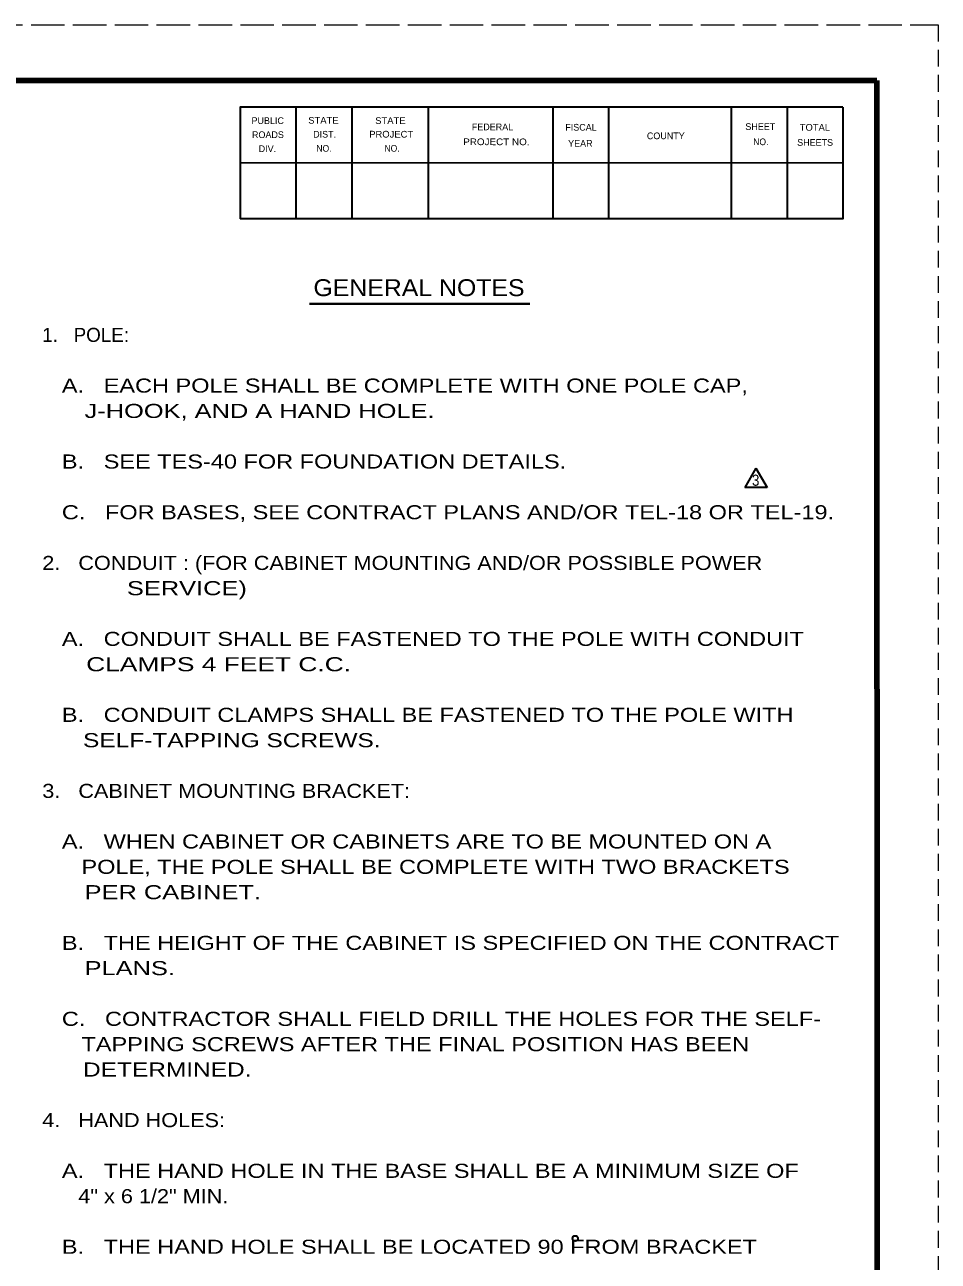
# Model space of a CAD drawing. Extents: x -1 to 679, y -228 to 440.
# Drawn here: x 515.4 to 679, y 218.8 to 440.2 of the extents above; entities that cross this region are included whole.
import ezdxf

# ---------------------------------------------------------------- set-up
doc = ezdxf.new("R2010")
doc.units = 0
doc.linetypes.add('LONG_DASHED', pattern=[7.5, 6, -1.5])
doc.linetypes.add('MEDIUM_DASHED', pattern=[4.5, 3, -1.5])
doc.layers.add('1', color=7, linetype='Continuous', lineweight=35)
doc.layers.add('61', color=7, linetype='Continuous', lineweight=35)

msp = doc.modelspace()

# ---------------------------------------------------------------- linework, layer by layer
at = {"layer": '1', "linetype": 'MEDIUM_DASHED', "lineweight": 13}
msp.add_line((679.041, 440.237), (679.021, 0.217), dxfattribs=at)
at = {"layer": '1', "lineweight": 40}
msp.add_line((566.411, 390.257), (605.851, 390.257), dxfattribs=at)
at = {"layer": '1'}
for p, q in [((646.385, 360.85), (644.385, 357.386)), ((646.385, 360.85), (648.385, 357.386)), ((648.385, 357.386), (644.385, 357.386))]:
    msp.add_line(p, q, dxfattribs=at)
msp.add_circle((614.003, 222.892), 0.481, dxfattribs=at)
at = {"layer": '61', "linetype": 'LONG_DASHED', "lineweight": 13}
msp.add_line((-0.979, 440.237), (679.041, 440.237), dxfattribs=at)
at = {"layer": '61', "lineweight": 158}
msp.add_line((668.061, 430.237), (668.081, 10.197), dxfattribs=at)
at = {"layer": '61'}
for p, q in [((563.981, 425.477), (563.981, 405.477)), ((573.981, 425.477), (573.981, 405.477)), ((587.661, 425.477), (587.661, 405.477)), ((609.981, 425.477), (609.981, 405.477)), ((619.981, 425.477), (619.981, 405.477)), ((641.961, 425.497), (641.961, 405.497)), ((651.961, 425.497), (651.961, 405.497)), ((661.981, 415.457), (553.961, 415.477))]:
    msp.add_line(p, q, dxfattribs=at)
at = {"layer": '61', "lineweight": 158}
msp.add_lwpolyline([(668.061, 430.237), (29.021, 430.237), (29.021, 10.217)], dxfattribs=at)
at = {"layer": '61'}
for points in [[(661.961, 425.497), (553.981, 425.477), (553.981, 405.477)], [(661.961, 425.497), (661.961, 405.497), (553.981, 405.477)]]:
    msp.add_lwpolyline(points, dxfattribs=at)

# ---------------------------------------------------------------- texts
at = {"layer": '1'}
for s, height, width, p in [('GENERAL NOTES', 3.024, 1.1, (567.111, 391.637)), ('   A.   EACH POLE SHALL BE COMPLETE WITH ONE POLE CAP,', 2.52, 1.25, (518.531, 374.357)), ('      J-HOOK, AND A HAND HOLE.', 2.52, 1.35, (518.531, 369.817)), ('   B.   SEE TES-40 FOR FOUNDATION DETAILS.', 2.52, 1.25, (518.531, 360.757)), ('3', 2, 0.9, (645.66, 357.67)), ('   C.   FOR BASES, SEE CONTRACT PLANS AND/OR TEL-18 OR TEL-19.', 2.52, 1.25, (518.531, 351.677)), ('2.   CONDUIT : (FOR CABINET MOUNTING AND/OR POSSIBLE POWER', 2.52, 1.15, (518.531, 342.597)), ('            SERVICE)', 2.52, 1.35, (518.531, 338.077)), ('   A.   CONDUIT SHALL BE FASTENED TO THE POLE WITH CONDUIT', 2.52, 1.25, (518.531, 328.997)), ('      CLAMPS 4 FEET C.C.', 2.52, 1.4, (518.531, 324.457)), ('   B.   CONDUIT CLAMPS SHALL BE FASTENED TO THE POLE WITH', 2.52, 1.25, (518.531, 315.397)), ('      SELF-TAPPING SCREWS.', 2.52, 1.3, (518.531, 310.857)), ('3.   CABINET MOUNTING BRACKET:', 2.52, 1.15, (518.531, 301.777)), ('   A.   WHEN CABINET OR CABINETS ARE TO BE MOUNTED ON A', 2.52, 1.25, (518.531, 292.717)), ('      POLE, THE POLE SHALL BE COMPLETE WITH TWO BRACKETS', 2.52, 1.25, (518.531, 288.177)), ('      PER CABINET.', 2.52, 1.35, (518.531, 283.637)), ('   B.   THE HEIGHT OF THE CABINET IS SPECIFIED ON THE CONTRACT', 2.52, 1.25, (518.531, 274.557)), ('      PLANS.', 2.52, 1.35, (518.531, 270.037)), ('   C.   CONTRACTOR SHALL FIELD DRILL THE HOLES FOR THE SELF-', 2.52, 1.25, (518.531, 260.957)), ('      TAPPING SCREWS AFTER THE FINAL POSITION HAS BEEN', 2.52, 1.25, (518.531, 256.417)), ('      DETERMINED.', 2.52, 1.3, (518.531, 251.877)), ('4.   HAND HOLES:', 2.52, 1.15, (518.531, 242.817)), ('   A.   THE HAND HOLE IN THE BASE SHALL BE A MINIMUM SIZE OF', 2.52, 1.25, (518.531, 233.737)), ('      4" x 6 1/2" MIN.', 2.52, 1.15, (518.531, 229.197)), ('   B.   THE HAND HOLE SHALL BE LOCATED 90 FROM BRACKET', 2.52, 1.25, (518.531, 220.137))]:
    msp.add_text(s, height=height, dxfattribs=dict(at, width=width)).set_placement(p)
msp.add_text('1.   POLE:', height=2.52, dxfattribs=at).set_placement((518.531, 383.437))
at = {"layer": '61'}
for s, rotation, p in [('PUBLIC', 0.033, (556.021, 422.457)), ('ROADS', 0.124, (556.101, 419.937)), ('DIST.', 0.056, (567.061, 420.017)), ('FEDERAL', 0.007, (595.481, 421.337)), ('FISCAL', 359.942, (612.221, 421.277)), ('COUNTY', 0.069, (626.841, 419.737)), ('SHEET', 0.059, (644.481, 421.397)), ('DIV.', 359.932, (557.301, 417.437)), ('YEAR', 0.105, (612.741, 418.377)), ('SHEETS', 359.959, (653.761, 418.557))]:
    msp.add_text(s, height=1.201, rotation=rotation, dxfattribs=at).set_placement(p)
for s, rotation, width, p in [('STATE', 0.059, 1.05, (566.181, 422.517)), ('STATE', 0.059, 1.05, (578.181, 422.457)), ('PROJECT', 359.908, 1.05, (577.101, 420.037)), ('TOTAL', 359.926, 1.05, (654.221, 421.257)), ('NO.', 359.852, 0.95, (567.641, 417.497)), ('NO.', 0.225, 0.95, (579.841, 417.497)), ('PROJECT NO.', 359.922, 1.1, (593.941, 418.677)), ('NO.', 359.852, 0.95, (645.901, 418.677))]:
    msp.add_text(s, height=1.201, rotation=rotation, dxfattribs=dict(at, width=width)).set_placement(p)

doc.saveas('drawing.dxf')
